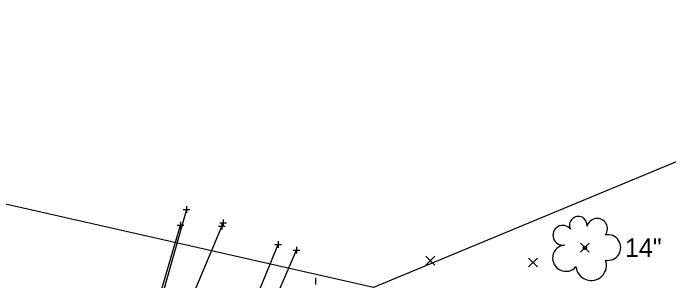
# Model space of a CAD drawing. Extents: x 160138 to 160780, y 488720 to 491073.
# Drawn here: x 160437.1 to 160535.3, y 489701.6 to 489741.6 of the extents above; entities that cross this region are included whole.
import ezdxf

# ---------------------------------------------------------------- set-up
doc = ezdxf.new("R2010")
doc.units = 0
for name, color, linetype in [('_CIVIL_CONSTRUCTION', 7, 'Continuous'), ('GE_X_Alignment_500_Bearings', 7, 'Continuous'), ('GE_X_Alignment_500_Stations', 7, 'Continuous'), ('PM_X_Dotted_Line', 7, 'Continuous'), ('PM_X_Lane_Line', 7, 'Continuous'), ('RD_X_Concrete_Pad', 7, 'Continuous'), ('SC_Scratch1', 7, 'Continuous'), ('SV_X_Random_Point', 7, 'Continuous'), ('SV_X_Terrain_Boundary', 7, 'Continuous'), ('VG_X_Text', 7, 'Continuous')]:
    doc.layers.add(name, color=color, linetype=linetype)

msp = doc.modelspace()

# ---------------------------------------------------------------- linework, layer by layer
at = {"layer": '_CIVIL_CONSTRUCTION'}
for p, q in [((160522.037, 489705.878), (160523.37, 489707.213)), ((160522.037, 489707.213), (160523.37, 489705.878)), ((160498.923, 489703.938), (160500.256, 489705.272)), ((160498.923, 489705.272), (160500.256, 489703.938)), ((160514.268, 489703.676), (160515.601, 489705.011)), ((160514.268, 489705.011), (160515.601, 489703.676))]:
    msp.add_line(p, q, dxfattribs=at)
at = {"layer": 'GE_X_Alignment_500_Bearings'}
msp.add_lwpolyline([(160440.742, 489637.043), (160446.015, 489655.554), (160450.316, 489669.375), (160457.69, 489694.634), (160462.173, 489709.925)], dxfattribs=at)
at = {"layer": 'GE_X_Alignment_500_Stations'}
msp.add_lwpolyline([(160450.023, 489634.057), (160456.121, 489652.731), (160460.286, 489661.827), (160465.917, 489674.569), (160472.713, 489690.364), (160479.522, 489706.201)], dxfattribs=at)
at = {"layer": 'PM_X_Dotted_Line'}
msp.add_lwpolyline([(160449.962, 489666.566), (160450.316, 489669.375), (160457.69, 489694.634), (160462.173, 489709.925)], dxfattribs=at)
at = {"layer": 'PM_X_Lane_Line'}
msp.add_lwpolyline([(160468.561, 489710.284), (160458.933, 489687.435), (160449.314, 489664.193), (160446.015, 489655.554), (160440.742, 489637.043)], dxfattribs=at)
at = {"layer": 'RD_X_Concrete_Pad'}
msp.add_lwpolyline([(160463.105, 489712.272), (160453.145, 489677.294), (160447.365, 489655.602), (160453.48, 489653.676), (160456.212, 489659.819), (160462.58, 489673.711), (160469.801, 489689.985), (160476.812, 489707.044)], dxfattribs=at)
at = {"layer": 'SC_Scratch1'}
msp.add_circle((160522.703, 489706.546), 0.24, dxfattribs=at)
for centre, radius, start, end in [((160521.72, 489709.913), 1.317, 354.0047, 205.97412), ((160524.53, 489709.375), 1.553, 323.82996, 165.0376), ((160519.394, 489708.41), 1.471, 39.06254, 279.54124), ((160526.164, 489706.582), 1.915, 259.14531, 101.45961), ((160519.85, 489704.997), 1.974, 96.17219, 320.57371), ((160523.65, 489703.941), 2.284, 184.94757, 19.45715)]:
    msp.add_arc(centre, radius, start, end, dxfattribs=at)
at = {"layer": 'SV_X_Random_Point'}
for p, q in [((160462.605, 489712.272), (160463.605, 489712.272)), ((160463.105, 489712.772), (160463.105, 489711.772)), ((160463.105, 489712.272), (160463.105, 489712.272)), ((160461.673, 489709.925), (160462.673, 489709.925)), ((160461.673, 489709.925), (160462.673, 489709.925)), ((160462.173, 489710.425), (160462.173, 489709.425)), ((160462.173, 489710.425), (160462.173, 489709.425)), ((160462.173, 489709.925), (160462.173, 489709.925)), ((160462.173, 489709.925), (160462.173, 489709.925)), ((160468.061, 489710.284), (160469.061, 489710.284)), ((160468.351, 489710.266), (160468.351, 489709.266)), ((160468.561, 489710.784), (160468.561, 489709.784)), ((160468.561, 489710.284), (160468.561, 489710.284)), ((160467.851, 489709.766), (160468.851, 489709.766)), ((160468.351, 489709.766), (160468.351, 489709.766)), ((160476.312, 489707.044), (160477.312, 489707.044)), ((160476.812, 489707.544), (160476.812, 489706.544)), ((160476.812, 489707.044), (160476.812, 489707.044)), ((160479.022, 489706.201), (160480.022, 489706.201)), ((160479.522, 489706.701), (160479.522, 489705.701)), ((160479.522, 489706.201), (160479.522, 489706.201)), ((160482.364, 489702.049), (160482.364, 489701.049))]:
    msp.add_line(p, q, dxfattribs=at)
at = {"layer": 'SV_X_Terrain_Boundary'}
msp.add_lwpolyline([(160560.406, 489729.318), (160491.054, 489700.611), (160398.91, 489721.406), (160369.477, 489735.484), (160345.102, 489741.595), (160340, 489741.437), (160332.016, 489740.129), (160312.105, 489734.793), (160313.355, 489709.705), (160316.289, 489695.424), (160319.472, 489684.931), (160347.565, 489655.198), (160408.831, 489644.698), (160473.475, 489628.861), (160504.758, 489630.54), (160514.912, 489637.894), (160547.865, 489638.238)], dxfattribs=at)

# ---------------------------------------------------------------- texts
at = {"layer": 'VG_X_Text'}
msp.add_text('14"', height=2.8, dxfattribs=at).set_placement((160528.703, 489705.146))

doc.saveas('drawing.dxf')
